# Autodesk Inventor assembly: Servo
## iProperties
Author: Philippe
Created: 2002-01
Part Number: Servo
Document SubType Name: Assemblage
Designer: Philippe
Control State: 0
Master: False
Checked Out: False
PropertySet Name: Design Tracking Control
Shininess: 41.0
Angle Display Precision: 2
Document Length Units: 11269
Document Angle Units: 11283
Document Time Units: 11279
Document Mass Units: 11290
Document Length Units Precision: 3
Document Angle Units Precision: 2
Compacted: False
PropertySet Name: _Private Model Information
Density: 0.0
Volumn: 0.0
Area: 0.0
PropertySet Name: Model Information
